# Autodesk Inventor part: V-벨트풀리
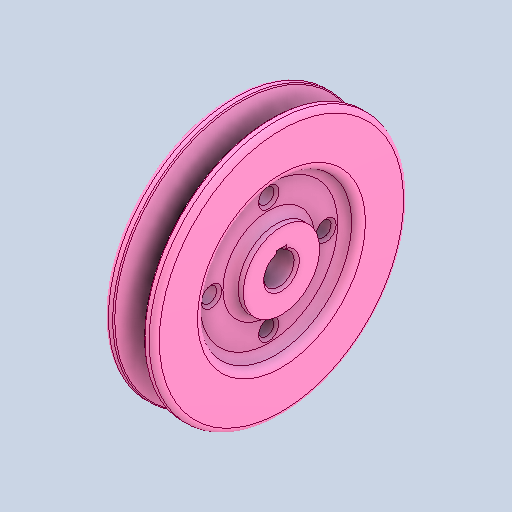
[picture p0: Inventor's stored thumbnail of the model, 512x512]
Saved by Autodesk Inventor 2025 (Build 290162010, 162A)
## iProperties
Created: 2024-07
Part Number: V-벨트풀리
Material: 강철, 연강
Document SubType Name: Modeling
Designer: 학생
Density: 7.86 g/cm^3
Appearance: 기본값
Author: jhkim
Sending System: Autodesk Inventor 2025
Preprocessor: ST-DEVELOPER v20
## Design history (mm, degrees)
feature "솔리드1"
node "솔리드2"
